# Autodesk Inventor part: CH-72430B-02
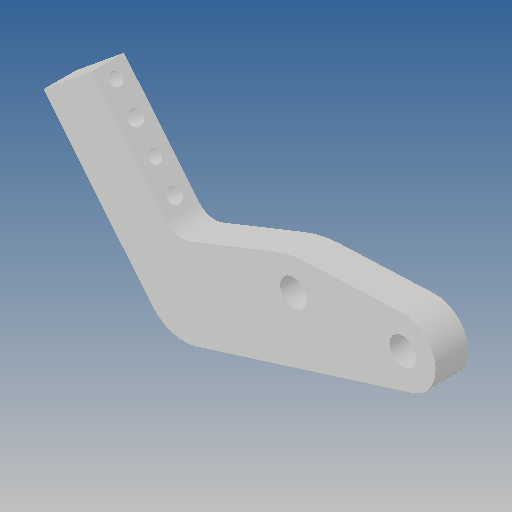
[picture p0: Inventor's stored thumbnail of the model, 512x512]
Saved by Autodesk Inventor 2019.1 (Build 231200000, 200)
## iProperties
Created: 2012-10
Part Number: CH-72430B-02
Material: Ogólny
Document SubType Name: Modeling
Designer: CADENGINEERING4
Density: 1 g/cm^3
Appearance: Domyślna
Author: CADENGINEERING4
Revision Number: ÈÎºÎ
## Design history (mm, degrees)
feature "ÇÐ³ý-À­Éì1"
node "Bryła1"
